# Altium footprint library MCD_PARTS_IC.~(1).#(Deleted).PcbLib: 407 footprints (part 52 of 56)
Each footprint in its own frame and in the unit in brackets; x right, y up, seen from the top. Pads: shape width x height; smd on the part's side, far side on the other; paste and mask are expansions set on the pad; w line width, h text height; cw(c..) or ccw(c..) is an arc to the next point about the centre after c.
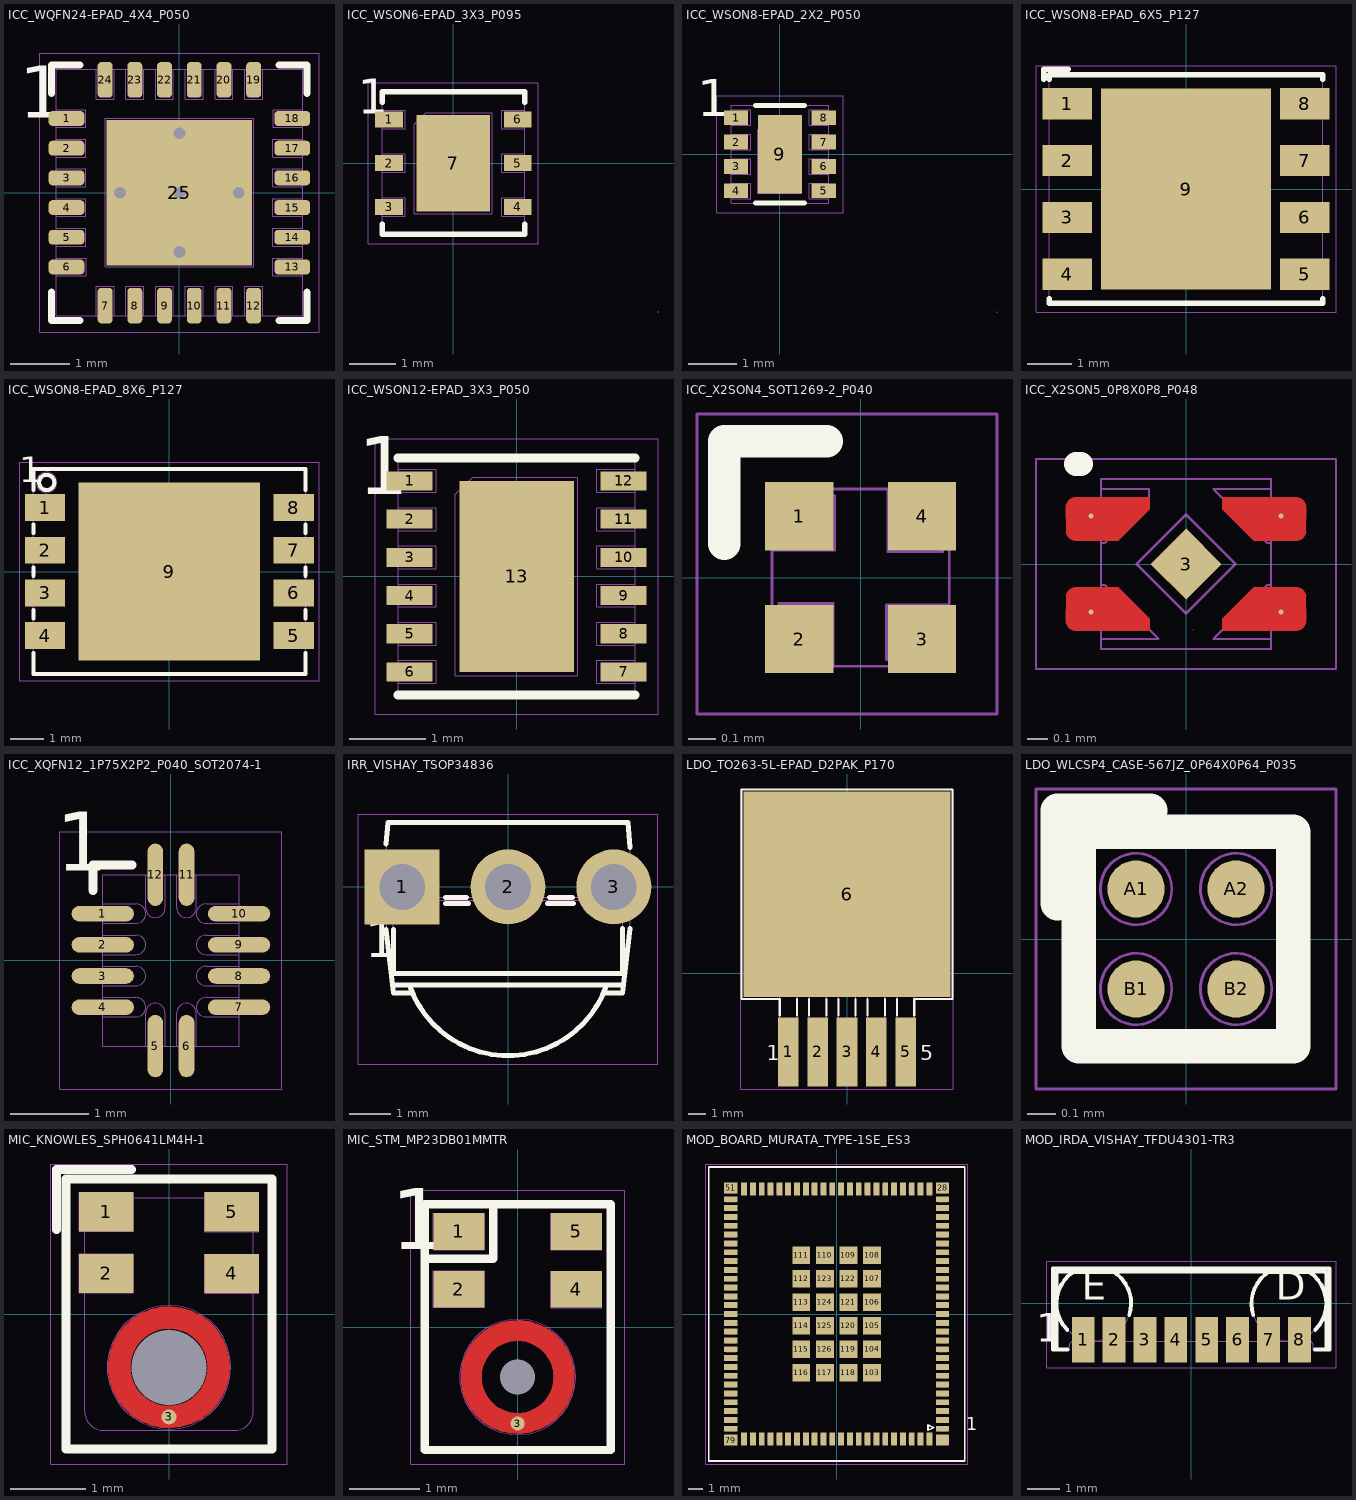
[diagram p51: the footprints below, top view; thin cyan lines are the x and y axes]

## ICC_WQFN24-EPAD_4X4_P050 [mm] "MCD-04320"
height 0.8
pads (25):
  rrect50% 0.6x0.25 smd mask+0.05: 1(-1.9,1.25) 2(-1.9,0.75) 3(-1.9,0.25) 4(-1.9,-0.25) 5(-1.9,-0.75) 6(-1.9,-1.25) 13(1.9,-1.25) 14(1.9,-0.75) 15(1.9,-0.25) 16(1.9,0.25) 17(1.9,0.75) 18(1.9,1.25)
  rrect50% 0.25x0.6 smd mask+0.05: 7(-1.25,-1.9) 8(-0.75,-1.9) 9(-0.25,-1.9) 10(0.25,-1.9) 11(0.75,-1.9) 12(1.25,-1.9) 19(1.25,1.9) 20(0.75,1.9) 21(0.25,1.9) 22(-0.25,1.9) 23(-0.75,1.9) 24(-1.25,1.9)
  rect 2.45x2.45 smd paste-10 mask+0.05: 25(0,0)
via 0,0 diameter 0.45 hole 0.2
via -1,0 diameter 0.45 hole 0.2
via 0,1 diameter 0.45 hole 0.2
via 1,0 diameter 0.45 hole 0.2
via 0,-1 diameter 0.45 hole 0.2
Top Overlay:
  lines w0.12: -2.15,-1.675 -2.15,-2.15 -1.675,-2.15 ; -2.15,1.675 -2.15,2.15 -1.675,2.15 ; 1.675,-2.15 2.15,-2.15 2.15,-1.675 ; 1.675,2.15 2.15,2.15 2.15,1.675
  text "1" at -2.7,0.975 h1.5
Top Paste:
  rectangle: -1.1,0.1 -0.1,1.1
  region: -0.1,-1.1 -0.1,-0.1 -1.1,-0.1 -1.1,-1.1
  region: 1.1,-0.1 0.1,-0.1 0.1,-1.1 1.1,-1.1
  region: 0.1,1.1 0.1,0.1 1.1,0.1 1.1,1.1
M14-Top Assembly:
  lines w0.01: -2.075,-1.4 -1.575,-1.4 -1.575,-1.1 -2.075,-1.1 ; -2.075,-0.9 -1.575,-0.9 -1.575,-0.6 -2.075,-0.6 ; -2.075,-0.4 -1.575,-0.4 -1.575,-0.1 -2.075,-0.1 ; -2.075,0.1 -1.575,0.1 -1.575,0.4 -2.075,0.4 ; -2.075,0.6 -1.575,0.6 -1.575,0.9 -2.075,0.9 ; -2.075,1.1 -1.575,1.1 -1.575,1.4 -2.075,1.4 ; -1.4,-2.075 -1.4,-1.575 -1.1,-1.575 -1.1,-2.075 ; -1.4,2.075 -1.4,1.575 -1.1,1.575 -1.1,2.075 ; -0.9,-2.075 -0.9,-1.575 -0.6,-1.575 -0.6,-2.075 ; -0.9,2.075 -0.9,1.575 -0.6,1.575 -0.6,2.075 ; -0.4,-2.075 -0.4,-1.575 -0.1,-1.575 -0.1,-2.075 ; -0.4,2.075 -0.4,1.575 -0.1,1.575 -0.1,2.075 ; 0.1,-2.075 0.1,-1.575 0.4,-1.575 0.4,-2.075 ; 0.1,2.075 0.1,1.575 0.4,1.575 0.4,2.075 ; 0.6,-2.075 0.6,-1.575 0.9,-1.575 0.9,-2.075 ; 0.6,2.075 0.6,1.575 0.9,1.575 0.9,2.075 ; 1.1,-2.075 1.1,-1.575 1.4,-1.575 1.4,-2.075 ; 1.1,2.075 1.1,1.575 1.4,1.575 1.4,2.075 ; 2.075,-1.4 1.575,-1.4 1.575,-1.1 2.075,-1.1 ; 2.075,-0.9 1.575,-0.9 1.575,-0.6 2.075,-0.6 ; 2.075,-0.4 1.575,-0.4 1.575,-0.1 2.075,-0.1 ; 2.075,0.1 1.575,0.1 1.575,0.4 2.075,0.4 ; 2.075,0.6 1.575,0.6 1.575,0.9 2.075,0.9 ; 2.075,1.1 1.575,1.1 1.575,1.4 2.075,1.4 ; -2.075,-2.075 -2.075,2.075 2.075,2.075 2.075,-2.075 -2.075,-2.075 ; -1.25,-1.25 1.25,-1.25 1.25,1.25 -1.25,1.25 -1.25,-1.25
  text "'.Designator'" at -2,-0.5 h0.75
  text "6" at -2.025,-1.125 h0.65
  text "24" at -1.58,1.625 h0.65
  text "19" at 0.97,1.625 h0.65
  text "18" at 2.025,0.975 h0.65
  text "13" at 2.025,-1.525 h0.65
  text "12" at 0.975,-2.025 h0.65
  text "7" at -1.4,-2.025 h0.65
  text "1" at -2.05,1.325 h0.65
  text "25" at -0.3,-0.225 h0.65
M16-Top Courtyard:
  lines w0.01: -2.35,-2.35 2.35,-2.35 2.35,2.35 -2.35,2.35 -2.35,-2.35
3D body "TXS02612RTWR_3D.stp": height 0.8, standoff 0, extent -2,-2 2,2

## ICC_WSON6-EPAD_3X3_P095 [mm] "MCD-02563"
height 0.8
pads (7):
  rect 0.6x0.35 smd paste+0 mask+0.05: 1(-1.4,0.95) 2(-1.4,0) 3(-1.4,-0.95) 4(1.4,-0.95) 5(1.4,0) 6(1.4,0.95)
  rect 1.6x2.1 smd paste+0 mask+0.05: 7(0,0)
Top Overlay:
  lines w0.12: -1.55,-1.325 -1.55,-1.55 1.55,-1.55 1.55,-1.325 ; -1.55,1.325 -1.55,1.55 1.55,1.55 1.55,1.325
  text "1" at -2.075,0.825 h1.3
M14-Top Assembly:
  lines w0.01: -1.55,-1.15 -1.05,-1.15 -1.05,-0.75 -1.55,-0.75 ; -1.55,-0.2 -1.05,-0.2 -1.05,0.2 -1.55,0.2 ; -1.55,0.75 -1.05,0.75 -1.05,1.15 -1.55,1.15 ; 1.55,-1.15 1.05,-1.15 1.05,-0.75 1.55,-0.75 ; 1.55,-0.2 1.05,-0.2 1.05,0.2 1.55,0.2 ; 1.55,0.75 1.05,0.75 1.05,1.15 1.55,1.15 ; -0.6,1.1 0.85,1.1 0.85,-1.1 -0.85,-1.1 -0.85,0.85 -0.6,1.1 ; -0.6,1.1 -0.6,1.1 ; -1.55,-1.55 1.55,-1.55 1.55,1.55 -1.55,1.55 -1.55,-1.55
  text "6" at 1.2,0.8 h0.5
  text "4" at 1.2,-1.1 h0.5
  text "'.Designator'" at -2,-0.5 h0.75
  text "1" at -1.4,0.8 h0.5
  text "3" at -1.4,-1.1 h0.5
M16-Top Courtyard:
  lines w0.01: 4.45,-3.25 4.45,-3.225 ; -1.85,-1.75 -1.85,1.75 1.85,1.75 1.85,-1.75 -1.85,-1.75
3D body: height 0.8, standoff 0, extent -1.55,-1.55 1.55,1.55
3D body: height 0.81, standoff 0.8, extent -1.325,0.926 -0.927,1.325
3D body "User Library-WSON-6.STEP": height 0.75, standoff 0, extent -1.51,-1.5 1.51,1.5

## ICC_WSON8-EPAD_2X2_P050 [mm] "MCD-02194"
height 0.8
pads (9):
  rect 0.5x0.3 smd paste+0 mask+0.05: 1(-0.9,0.75) 2(-0.9,0.25) 3(-0.9,-0.25) 4(-0.9,-0.75) 5(0.9,-0.75) 6(0.9,-0.25) 7(0.9,0.25) 8(0.9,0.75)
  rect 0.9x1.6 smd paste+0 mask+0.05: 9(0,0)
Top Overlay:
  lines w0.1: -0.5,-1 0.5,-1 ; -0.5,1 0.5,1
  text "1" at -1.7,0.525 h1.3
M14-Top Assembly:
  lines w0.01: -1,-0.91 -0.6,-0.91 -0.6,-0.59 -1,-0.59 ; -1,-0.41 -0.6,-0.41 -0.6,-0.09 -1,-0.09 ; -1,0.09 -0.6,0.09 -0.6,0.41 -1,0.41 ; -1,0.59 -0.6,0.59 -0.6,0.91 -1,0.91 ; -1,-1 1,-1 1,1 -1,1 -1,-1 ; -0.45,-0.8 -0.45,0.5 -0.15,0.8 0.45,0.8 0.45,-0.8 -0.45,-0.8 ; 0.6,-0.91 0.6,-0.59 1,-0.59 1,-0.91 0.6,-0.91 ; 0.6,-0.41 0.6,-0.09 1,-0.09 1,-0.41 0.6,-0.41 ; 0.6,0.09 0.6,0.41 1,0.41 1,0.09 0.6,0.09 ; 0.6,0.59 0.6,0.91 1,0.91 1,0.59 0.6,0.59
  text "'.Designator'" at -2,-0.5 h0.75
  text "1" at -0.9,0.575 h0.5
  text "4" at -0.925,-0.9 h0.5
  text "5" at 0.7,-0.9 h0.5
  text "8" at 0.7,0.575 h0.5
M16-Top Courtyard:
  lines w0.01: 4.45,-3.25 4.45,-3.225 ; -1.3,-1.2 -1.3,1.2 1.3,1.2 1.3,-1.2 -1.3,-1.2
3D body "User Library-SON8-2x2mm-1.STEP": height 0.77, standoff -0.03, extent -1,-1 1,1
3D body: height 0.8, standoff 0, extent -1,-1 1,1
3D body: height 0.81, standoff 0.8, extent -0.873,0.526 -0.475,0.925

## ICC_WSON8-EPAD_6X5_P127 [mm] "MCD-02498"
height 0.8
pads (9):
  rect 1.1x0.7 smd paste+0 mask+0.05: 1(-2.65,1.905) 2(-2.65,0.635) 3(-2.65,-0.635) 4(-2.65,-1.905) 5(2.65,-1.905) 6(2.65,-0.635) 7(2.65,0.635) 8(2.65,1.905)
  rect 3.8x4.5 smd paste+0 mask+0.05: 9(0,0)
Top Overlay:
  lines w0.12: -3.175,2.45 -3.175,2.675 -2.625,2.675 ; -3.05,-2.45 -3.05,-2.55 3.05,-2.55 3.05,-2.45 ; -3.05,2.45 -3.05,2.55 3.05,2.55 3.05,2.45
M14-Top Assembly:
  lines w0.01: -3.05,-2.159 -2.4,-2.159 -2.4,-1.651 -3.05,-1.651 ; -3.05,-0.889 -2.4,-0.889 -2.4,-0.381 -3.05,-0.381 ; -3.05,0.381 -2.4,0.381 -2.4,0.889 -3.05,0.889 ; -3.05,1.651 -2.4,1.651 -2.4,2.159 -3.05,2.159 ; 3.047,-2.156 2.397,-2.156 2.397,-1.648 3.047,-1.648 ; 3.047,-0.886 2.397,-0.886 2.397,-0.378 3.047,-0.378 ; 3.047,0.384 2.397,0.384 2.397,0.892 3.047,0.892 ; 3.047,1.654 2.397,1.654 2.397,2.162 3.047,2.162 ; -3.05,-2.55 -3.05,2.55 3.05,2.55 3.05,-2.55 -3.05,-2.55 ; -1.725,-2.025 -1.725,2.025 1.725,2.025 1.725,-2.025 -1.725,-2.025
  text "8" at 2.636,1.668 h0.75
  text "7" at 2.639,0.398 h0.75
  text "6" at 2.635,-0.872 h0.75
  text "5" at 2.635,-2.138 h0.75
  text "4" at -2.96,-2.145 h0.75
  text "3" at -2.951,-0.872 h0.75
  text "2" at -2.954,0.394 h0.75
  text "1" at -2.882,1.664 h0.75
  text "9" at -0.158,-0.237 h0.75
  text "'.Designator'" at -2,-0.5 h0.75
M16-Top Courtyard:
  lines w0.01: -3.35,-2.75 -3.35,2.75 3.35,2.75 3.35,-2.75 -3.35,-2.75
3D body "8 WSON.STEP": height 0.75, standoff 0, extent -3,-2.5 3,2.5

## ICC_WSON8-EPAD_8X6_P127 [mm]
height 0.8
pads (9):
  rect 1.2x0.8 smd paste+0 mask+0.05: 1(-3.7,1.905) 2(-3.7,0.635) 3(-3.7,-0.635) 4(-3.7,-1.905) 5(3.7,-1.905) 6(3.7,-0.635) 7(3.7,0.635) 8(3.7,1.905)
  rect 5.4x5.3 smd paste+0 mask+0.05: 9(0,0)
Top Overlay:
  circle w0.12: c-3.65,2.65 r0.226
  lines w0.12: -4.05,-2.425 -4.05,-3.05 4.05,-3.05 4.05,-2.425 ; -4.05,-1.4 -4.05,-1.15 ; -4.05,-0.125 -4.05,0.125 ; -4.05,1.15 -4.05,1.4 ; -4.05,2.425 -4.05,3.05 4.05,3.05 4.05,2.425 ; 4.05,-1.4 4.05,-1.15 ; 4.05,-0.125 4.05,0.125 ; 4.05,1.15 4.05,1.4
  text "1" at -4.475,2.4 h1.3
M14-Top Assembly:
  circle w0.01: c-3.65,2.65 r0.304
  lines w0.01: -4.05,-2.159 -3.45,-2.159 -3.45,-1.651 -4.05,-1.651 ; -4.05,-0.889 -3.45,-0.889 -3.45,-0.381 -4.05,-0.381 ; -4.05,0.381 -3.45,0.381 -3.45,0.889 -4.05,0.889 ; -4.05,1.651 -3.45,1.651 -3.45,2.159 -4.05,2.159 ; 4.05,-2.159 3.45,-2.159 3.45,-1.651 4.05,-1.651 ; 4.05,-0.889 3.45,-0.889 3.45,-0.381 4.05,-0.381 ; 4.05,0.381 3.45,0.381 3.45,0.889 4.05,0.889 ; 4.05,1.651 3.45,1.651 3.45,2.159 4.05,2.159 ; -4.05,-3.05 -4.05,3.05 4.05,3.05 4.05,-3.05 -4.05,-3.05 ; -2.4,-2.35 2.4,-2.35 2.4,2.35 -2.4,2.35 -2.4,-2.35
  text "'.Designator'" at -2,0.5 h0.75
  text "9" at -0.15,-0.2 h0.75
  text "1" at -3.85,1.65 h0.75
  text "4" at -3.9,-2.15 h0.75
  text "5" at 3.6,-2.15 h0.75
  text "8" at 3.6,1.65 h0.75
M16-Top Courtyard:
  lines w0.01: -4.45,-3.25 -4.45,2.35 -4.45,3.25 4.45,3.25 4.45,2.8 4.45,-3.225 4.45,-3.25 -4.45,-3.25
3D body "WSON-8_6x8mm.STEP": height 0.81, standoff -0.07, extent -4,-3 4,3
3D body: height 0.8, standoff 0, extent -4.05,-3.05 4.05,3.05
3D body: height 0.81, standoff 0.8, extent -3.648,2.25 -3.25,2.65

## ICC_WSON12-EPAD_3X3_P050 [mm]
height 0.8
pads (13):
  rect 0.6x0.25 smd paste+0 mask+0.05: 1(-1.4,1.25) 2(-1.4,0.75) 3(-1.4,0.25) 4(-1.4,-0.25) 5(-1.4,-0.75) 6(-1.4,-1.25) 7(1.4,-1.25) 8(1.4,-0.75) 9(1.4,-0.25) 10(1.4,0.25) 11(1.4,0.75) 12(1.4,1.25)
  rect 1.5x2.5 smd paste+0 mask+0.05: 13(0,0)
Top Overlay:
  lines w0.12: -1.55,-1.55 1.55,-1.55 ; -1.55,1.55 1.55,1.55
  text "1" at -2.075,0.825 h1.3
M14-Top Assembly:
  lines w0.01: -1.55,-1.4 -1.05,-1.4 -1.05,-1.1 -1.55,-1.1 ; -1.55,-0.9 -1.05,-0.9 -1.05,-0.6 -1.55,-0.6 ; -1.55,-0.4 -1.05,-0.4 -1.05,-0.1 -1.55,-0.1 ; -1.55,0.1 -1.05,0.1 -1.05,0.4 -1.55,0.4 ; -1.55,0.6 -1.05,0.6 -1.05,0.9 -1.55,0.9 ; -1.55,1.1 -1.05,1.1 -1.05,1.4 -1.55,1.4 ; 1.55,-1.4 1.05,-1.4 1.05,-1.1 1.55,-1.1 ; 1.55,-0.9 1.05,-0.9 1.05,-0.6 1.55,-0.6 ; 1.55,-0.4 1.05,-0.4 1.05,-0.1 1.55,-0.1 ; 1.55,0.1 1.05,0.1 1.05,0.4 1.55,0.4 ; 1.55,0.6 1.05,0.6 1.05,0.9 1.55,0.9 ; 1.55,1.1 1.05,1.1 1.05,1.4 1.55,1.4 ; -1.55,-1.55 1.55,-1.55 1.55,1.55 -1.55,1.55 -1.55,-1.55 ; -0.8,-1.3 -0.8,1.075 -0.575,1.3 0.8,1.3 0.8,-1.3 -0.8,-1.3
  text "13" at -0.225,-0.175 h0.5
  text "12" at 1.1,1.1 h0.5
  text "7" at 1.2,-1.4 h0.5
  text "'.Designator'" at -2,-0.5 h0.75
  text "1" at -1.4,1.1 h0.5
  text "6" at -1.4,-1.425 h0.5
M16-Top Courtyard:
  lines w0.01: -1.85,-1.8 -1.85,1.8 1.85,1.8 1.85,-1.8 -1.85,-1.8
3D body: height 0.81, standoff 0.8, extent -1.346,0.896 -0.946,1.296
3D body: height 0.8, standoff 0, extent -1.55,-1.55 1.55,1.55

## ICC_X2SON4_SOT1269-2_P040 [mm] "MCD-03125"
height 0.35
pads (4):
  rect 0.25x0.25 smd mask+0.05: 1(-0.225,0.225) 2(-0.225,-0.225) 3(0.225,-0.225) 4(0.225,0.225)
Top Overlay:
  lines w0.12: -0.5,0.125 -0.5,0.5 -0.475,0.5 -0.125,0.5
M14-Top Assembly:
  lines w0.01: -0.325,0.1 -0.095,0.1 -0.095,0.3 -0.275,0.3 cw(c-0.325,0.3) -0.325,0.25 ; -0.25,-0.325 ccw(c-0.3,-0.325) -0.3,-0.275 -0.3,-0.095 -0.1,-0.095 -0.1,-0.325 ; 0.1,0.325 0.1,0.095 0.3,0.095 0.3,0.275 cw(c0.3,0.325) 0.25,0.325 ; 0.325,-0.25 ccw(c0.325,-0.3) 0.275,-0.3 0.095,-0.3 0.095,-0.1 0.325,-0.1 ; -0.325,-0.325 0.325,-0.325 0.325,0.325 -0.325,0.325 -0.325,-0.325
  text "'.Designator'" at -2,-0.5 h0.75
  text "1" at -0.225,0.125 h0.25
  text "2" at -0.25,-0.275 h0.25
  text "3" at 0.15,-0.275 h0.25
  text "4" at 0.15,0.125 h0.25
M16-Top Courtyard:
  lines w0.01: -0.6,-0.5 0.5,-0.5 0.5,0.6 -0.6,0.6 -0.6,-0.5
3D body: height 0.36, standoff 0.35, extent -0.285,0.08 -0.085,0.28
3D body: height 0.35, standoff 0, extent -0.325,-0.325 0.325,0.325

## ICC_X2SON5_0P8X0P8_P048 [mm] "MCD-03119"
height 0.4
pads (5):
  round 0.025 smd mask+0.05: 1(-0.475,0.24) 2(-0.475,-0.24) 4(0.475,-0.24) 5(0.475,0.24)
  rect 0.25x0.25 smd rot 45 mask+0.05: 3(0,0)
Top Layer:
  region: 0.34,-0.115 0.18,-0.275 0.18,-0.335 0.55,-0.335 0.56,-0.335 0.578,-0.327 0.592,-0.313 0.6,-0.295 0.6,-0.285 0.6,-0.165 0.6,-0.155 0.592,-0.137 0.578,-0.123 0.56,-0.115 0.55,-0.115
  region: -0.34,-0.115 -0.18,-0.275 -0.18,-0.335 -0.55,-0.335 -0.56,-0.335 -0.578,-0.327 -0.592,-0.313 -0.6,-0.295 -0.6,-0.285 -0.6,-0.165 -0.6,-0.155 -0.592,-0.137 -0.578,-0.123 -0.56,-0.115 -0.55,-0.115
  region: 0.34,0.115 0.18,0.275 0.18,0.335 0.55,0.335 0.56,0.335 0.578,0.327 0.592,0.313 0.6,0.295 0.6,0.285 0.6,0.165 0.6,0.155 0.592,0.137 0.578,0.123 0.56,0.115 0.55,0.115
  region: -0.34,0.115 -0.18,0.275 -0.18,0.335 -0.55,0.335 -0.56,0.335 -0.578,0.327 -0.592,0.313 -0.6,0.295 -0.6,0.285 -0.6,0.165 -0.6,0.155 -0.592,0.137 -0.578,0.123 -0.56,0.115 -0.55,0.115
  lines w0.001: 0.035,-0.33 0.035,-0.33
Top Overlay:
  lines w0.12: -0.55,0.5 -0.525,0.5
M14-Top Assembly:
  lines w0.01: -0.425,-0.425 0.425,-0.425 0.425,0.425 -0.425,0.425 -0.425,-0.425 ; -0.425,-0.375 -0.425,-0.105 -0.407,-0.105 -0.137,-0.375 -0.425,-0.375 ; -0.425,0.105 -0.407,0.105 -0.186,0.326 -0.186,0.375 -0.425,0.375 -0.425,0.105 ; -0.247,0 0,-0.247 0.247,0 0,0.247 -0.247,0 ; 0.137,-0.375 0.407,-0.105 0.425,-0.105 0.425,-0.375 0.137,-0.375 ; 0.137,0.375 0.407,0.105 0.425,0.105 0.425,0.375 0.137,0.375
  text "4" at 0.25,-0.3 h0.25
  text "'.Designator'" at -2,-0.5 h0.75
  text "1" at -0.35,0.175 h0.25
  text "2" at -0.35,-0.325 h0.25
  text "3" at -0.05,-0.075 h0.25
  text "5" at 0.25,0.175 h0.25
M16-Top Courtyard:
  lines w0.01: -0.75,-0.525 -0.75,0.525 0.75,0.525 0.75,-0.525 -0.75,-0.525
3D body: height 0.41, standoff 0.4, extent -0.375,0.175 -0.175,0.375
3D body: height 0.4, standoff 0, extent -0.425,-0.425 0.425,0.425

## ICC_XQFN12_1P75X2P2_P040_SOT2074-1 [mm] "MCD-03404"
height 1
pads (12):
  rrect100% 0.8x0.2 smd mask+0.05: 1(-0.875,0.6) 2(-0.875,0.2) 3(-0.875,-0.2) 4(-0.875,-0.6) 7(0.875,-0.6) 8(0.875,-0.2) 9(0.875,0.2) 10(0.875,0.6)
  rrect100% 0.2x0.8 smd mask+0.05: 5(-0.2,-1.1) 6(0.2,-1.1) 11(0.2,1.1) 12(-0.2,1.1)
Top Overlay:
  lines w0.12: -1,0.9 -1,1.225 -0.5,1.225
  text "1" at -1.475,0.9 h1.3
M14-Top Assembly:
  lines w0.01: -0.875,-0.725 -0.45,-0.725 ccw(c-0.45,-0.6) -0.325,-0.6 ccw(c-0.45,-0.6) -0.45,-0.475 -0.875,-0.475 ; -0.875,-0.325 -0.45,-0.325 ccw(c-0.45,-0.2) -0.325,-0.2 ccw(c-0.45,-0.2) -0.45,-0.075 -0.875,-0.075 ; -0.875,0.075 -0.45,0.075 ccw(c-0.45,0.2) -0.325,0.2 ccw(c-0.45,0.2) -0.45,0.325 -0.875,0.325 ; -0.875,0.475 -0.45,0.475 ccw(c-0.45,0.6) -0.325,0.6 ccw(c-0.45,0.6) -0.45,0.725 -0.875,0.725 ; -0.325,-1.1 -0.325,-0.675 cw(c-0.2,-0.675) -0.2,-0.55 cw(c-0.2,-0.675) -0.075,-0.675 -0.075,-1.1 ; -0.325,1.1 -0.325,0.675 ccw(c-0.2,0.675) -0.2,0.55 ccw(c-0.2,0.675) -0.075,0.675 -0.075,1.1 ; 0.075,-1.1 0.075,-0.675 cw(c0.2,-0.675) 0.2,-0.55 cw(c0.2,-0.675) 0.325,-0.675 0.325,-1.1 ; 0.075,1.1 0.075,0.675 ccw(c0.2,0.675) 0.2,0.55 ccw(c0.2,0.675) 0.325,0.675 0.325,1.1 ; 0.875,-0.725 0.45,-0.725 cw(c0.45,-0.6) 0.325,-0.6 cw(c0.45,-0.6) 0.45,-0.475 0.875,-0.475 ; 0.875,-0.325 0.45,-0.325 cw(c0.45,-0.2) 0.325,-0.2 cw(c0.45,-0.2) 0.45,-0.075 0.875,-0.075 ; 0.875,0.075 0.45,0.075 cw(c0.45,0.2) 0.325,0.2 cw(c0.45,0.2) 0.45,0.325 0.875,0.325 ; 0.875,0.475 0.45,0.475 cw(c0.45,0.6) 0.325,0.6 cw(c0.45,0.6) 0.45,0.725 0.875,0.725 ; -0.875,-1.1 -0.875,1.1 0.875,1.1 0.875,-1.1 -0.875,-1.1 ; -0.75,-0.725 -0.75,-0.725 ; -0.75,-0.325 -0.75,-0.325 ; -0.75,0.075 -0.75,0.075 ; -0.75,0.475 -0.75,0.475 ; -0.325,-0.975 -0.325,-0.975 ; -0.075,0.975 -0.075,0.975 ; 0.075,-0.975 0.075,-0.975 ; 0.325,0.975 0.325,0.975 ; 0.75,-0.725 0.75,-0.725 ; 0.75,-0.325 0.75,-0.325 ; 0.75,0.075 0.75,0.075 ; 0.75,0.475 0.75,0.475
  text "1" at -0.8,0.4 h0.7
  text "'.Designator'" at -2,-0.5 h0.75
M16-Top Courtyard:
  lines w0.01: -1.425,-1.65 -1.425,1.65 1.425,1.65 1.425,-1.65 -1.425,-1.65
3D body: height 0.51, standoff 0.5, extent -0.699,0.625 -0.4,0.925
3D body: height 0.5, standoff 0, extent -0.875,-1.1 0.875,1.1

## IRR_VISHAY_TSOP34836 [mm] "MCD-01692"
height 8.25
pads (3):
  rect 1.8x1.8 hole 1.1 mask+0.05: 1(-2.54,0)
  round 1.8 hole 1.1 mask+0.05: 2(0,0) 3(2.54,0)
Top Overlay:
  lines w0.12: -2.925,-1.025 -2.75,-2.55 -2.29,-2.55 ; -2.925,1.025 -2.875,1.55 2.875,1.55 2.925,0.95 ; -2.774,-2.35 2.774,-2.35 ; -2.75,-1.025 -2.75,-2.075 2.75,-2.075 2.75,-1 ; -2.369,-2.348 ccw(c0,-1.55) 2.369,-2.348 ; -1.5,-0.4 -0.95,-0.4 ; -1.5,-0.25 -1,-0.25 ; 0.95,-0.4 1.575,-0.4 ; 1,-0.25 1.55,-0.25 ; 2.29,-2.55 2.75,-2.55 2.925,-1
  text "1" at -3.425,-1.975 h1.5
M14-Top Assembly:
  lines w0.01: -2.774,-2.35 2.774,-2.35 ; -2.369,-2.348 ccw(c0,-1.55) 2.369,-2.348 ; -2.29,-2.55 -2.75,-2.55 -3,-0.25 ; 2.29,-2.55 2.75,-2.55 3,-0.25 ; -3,-0.25 3,-0.25 ; -3,-0.25 -2.875,1.55 2.875,1.55 3,-0.25 ; -2.89,-0.25 -2.19,-0.25 -2.19,0.25 -2.89,0.25 -2.89,-0.25 ; -2.75,-2.075 -2.75,-0.325 2.75,-0.325 2.75,-2.075 -2.75,-2.075 ; -0.35,-0.25 0.35,-0.25 0.35,0.25 -0.35,0.25 -0.35,-0.25 ; 2.19,-0.25 2.89,-0.25 2.89,0.25 2.19,0.25 2.19,-0.25
  text "3" at 2.4,-0.25 h0.75
  text "2" at -0.175,-0.25 h0.75
  text "'.Designator'" at -2,-1.7 h0.75
  text "1" at -2.65,-0.25 h0.75
M16-Top Courtyard:
  lines w0.01: -3.6,-4.25 -3.6,1.75 3.6,1.75 3.6,-4.25 -3.6,-4.25
3D body: height 8.25, standoff 0, extent -3,-4.05 3,1.55
3D body "TSOP34836.stp": height 8.25, standoff -22.25, extent -3,-4 3,1.55

## LDO_TO263-5L-EPAD_D2PAK_P170 [mm]
height 4.6
pads (6):
  rect 1.2x4 smd mask+0.05: 1(-3.4,-4.575) 2(-1.7,-4.575) 3(0,-4.575) 4(1.7,-4.575) 5(3.4,-4.575)
  rect 12x11.9 smd mask+0.05: 6(0,4.575)
Top Overlay:
  lines w0.12: -3.9,-2.45 -3.9,-1.5 -6.125,-1.5 -6.125,-0.85 -6.125,10.65 6.125,10.65 6.125,-1.5 3.9,-1.5 3.9,-2.45 ; -2.9,-2.45 -2.9,-1.5 ; -2.2,-2.45 -2.2,-1.5 ; -1.2,-2.45 -1.2,-1.5 ; -0.5,-2.45 -0.5,-1.5 ; 0.5,-2.45 0.5,-1.5 ; 1.2,-2.45 1.2,-1.5 ; 2.2,-2.45 2.2,-1.5 ; 2.9,-2.45 2.9,-1.5
  text "5" at 4.25,-5.35 h1.5
  text "1" at -4.65,-5.35 h1.5
M14-Top Assembly:
  lines w0.01: -5.5,8.325 -5.5,9.325 -4.8,10.025 ; -5.5,8.325 -5.5,-0.875 5.5,-0.875 5.5,8.325 ; -5.5,8.325 0,8.325 5.5,8.325 ; -4.8,10.025 4.8,10.025 5.5,9.325 ; -4.8,10.025 -4.8,10.025 ; -3.9,-3.175 -2.9,-3.175 ; -3.9,-3.175 -3.9,-5.975 -2.9,-5.975 -2.9,-3.175 ; -3.9,-3.175 -3.9,-0.875 -2.9,-0.875 -2.9,-3.175 ; -3.9,-3.175 -2.9,-3.175 ; -2.2,-3.175 -1.2,-3.175 ; -2.2,-3.175 -2.2,-5.975 -1.2,-5.975 -1.2,-3.175 ; -2.2,-3.175 -2.2,-0.875 -1.2,-0.875 -1.2,-3.175 ; -2.2,-3.175 -1.2,-3.175 ; -0.5,-3.175 0.5,-3.175 ; -0.5,-3.175 -0.5,-0.875 0.5,-0.875 0.5,-3.175 ; -0.5,-3.175 -0.5,-5.975 0.5,-5.975 0.5,-3.175 ; -0.5,-3.175 0.5,-3.175 ; 1.2,-3.175 2.2,-3.175 ; 1.2,-3.175 1.2,-5.975 2.2,-5.975 2.2,-3.175 ; 1.2,-3.175 1.2,-0.875 2.2,-0.875 2.2,-3.175 ; 1.2,-3.175 2.2,-3.175 ; 2.9,-3.175 3.9,-3.175 ; 2.9,-3.175 2.9,-5.975 3.9,-5.975 3.9,-3.175 ; 2.9,-3.175 2.9,-0.875 3.9,-0.875 3.9,-3.175 ; 2.9,-3.175 3.9,-3.175 ; 5.5,8.325 5.5,9.325 ; 5.5,9.325 5.5,9.325
  text "'.Designator'" at -2,-0.5 h0.75
  text "2" at -2.125,-5.175 h1.5
  text "3" at -0.425,-5.175 h1.5
  text "1" at -3.525,-5.15 h1.5
  text "4" at 1.3,-5.2 h1.5
  text "5" at 3,-5.2 h1.5
M16-Top Courtyard:
  lines w0.01: -6.15,-6.725 -6.15,10.675 6.15,10.675 6.15,-6.725 -3.75,-6.725 -4.05,-6.725 -6.15,-6.725
3D body: height 4.6, standoff 0, extent -5.5,-0.875 5.5,10.025
3D body "TO-263-5.STEP": height 4.56, standoff 0, extent -5.13,-5.152 5.03,8.863

## LDO_WLCSP4_CASE-567JZ_0P64X0P64_P035 [mm]
height 0.33
pads (4):
  round 0.2 smd mask+0.038: A1(-0.175,0.175) A2(0.175,0.175) B1(-0.175,-0.175) B2(0.175,-0.175)
Top Overlay:
  lines w0.12: -0.45,0.125 -0.45,0.45 -0.125,0.45 ; -0.375,-0.375 -0.375,0.375 0.375,0.375 0.375,-0.375 -0.375,-0.375
M14-Top Assembly:
  circle w0.01: c-0.175,0.175 r0.125
  circle w0.01: c0.175,0.175 r0.125
  circle w0.01: c0.175,-0.175 r0.125
  circle w0.01: c-0.175,-0.175 r0.125
  lines w0.01: -0.32,-0.32 0.32,-0.32 0.32,0.32 -0.32,0.32 -0.32,-0.32
  text "A1" at -0.3,0.1 h0.3
  text "'.Designator'" at -2,-0.5 h0.75
M16-Top Courtyard:
  lines w0.01: -0.525,-0.525 -0.525,-0.05 -0.525,0.525 0.525,0.525 0.525,-0.525 -0.525,-0.525
3D body: height 0.33, standoff 0, extent -0.312,-0.312 0.313,0.313
3D body "WLCSP4.STEP": height 0.45, standoff -0.02, extent -0.337,-0.337 0.338,0.338

## MIC_KNOWLES_SPH0641LM4H-1 [mm] "MCD-01395"
height 1.08
pads (6):
  rect 0.725x0.522 smd mask+0.05: 1(-0.838,1.364) 2(-0.838,0.542) 4(0.838,0.542) 5(0.838,1.364)
  round 0.2 smd mask+0.05: 3(0,-1.373)
  round 0 hole 1 unplated mask+0.05: 6(0,-0.71)
Top Layer:
  circle w0.3: c0,-0.71 r0.663
Top Overlay:
  lines w0.12: -1.5,1.125 -1.5,1.925 -0.5,1.925 ; -1.375,-1.8 1.375,-1.8 1.375,1.8 -1.375,1.8 -1.375,-1.8
Bottom Overlay:
  circle w0.1: c0,-0.71 r0.654
M14-Top Assembly:
  circle w0.01: c0,-0.71 r0.825
  circle w0.01: c0,-0.71 r0.525
  circle w0.01: c0,-0.71 r0.175
  lines w0.01: -1.375,-1.8 -1.375,1.8 1.375,1.8 1.375,-1.8 -1.375,-1.8 ; -1.2,0.285 -0.475,0.285 -0.475,0.805 -1.2,0.805 -1.2,0.285 ; -1.2,1.105 -1.2,1.625 -0.475,1.625 -0.475,1.105 -1.2,1.105 ; -1.125,-1.3 ccw(c-0.875,-1.3) -0.875,-1.55 0.875,-1.55 ccw(c0.875,-1.3) 1.125,-1.3 1.125,1.3 ccw(c0.875,1.3) 0.875,1.55 -0.875,1.55 ccw(c-0.875,1.3) -1.125,1.3 -1.125,-1.3 ; 0.475,0.28 0.475,0.8 1.2,0.8 1.2,0.28 0.475,0.28 ; 0.475,1.1 1.2,1.1 1.2,1.62 0.475,1.62 0.475,1.1
  text "1" at -0.975,1.15 h0.7
  text "2" at -1,0.325 h0.7
  text "4" at 0.65,0.325 h0.7
  text "5" at 0.675,1.15 h0.7
  text "3" at -0.175,-1.6 h0.7
  text "'.Designator'" at 0,0 h0.75
M16-Top Courtyard:
  lines w0.01: -1.575,-2 1.575,-2 1.575,2 -1.575,2 -1.575,-2
3D body: height 0.3, standoff 0, extent -1.375,-1.8 1.375,1.8
3D body: height 1.08, standoff 0.31, extent -1.125,-1.55 1.125,1.55
3D body: height 1.09, standoff 1.08, extent -0.149,-0.85 0.15,-0.55

## MIC_STM_MP23DB01MMTR [mm]
height 1.08
pads (6):
  rect 0.725x0.522 smd mask+0.05: 1(-0.838,1.364) 2(-0.838,0.542) 4(0.838,0.542) 5(0.838,1.364)
  round 0.2 smd mask+0.05: 3(0,-1.373)
  round 0 hole 0.5 unplated mask+0.05: 6(0,-0.71)
Top Layer:
  circle w0.3: c0,-0.71 r0.663
Top Overlay:
  lines w0.12: -1.325,0.975 -0.35,0.975 -0.35,1.74 -0.36,1.75 ; -1.325,-1.75 1.325,-1.75 1.325,1.75 -1.325,1.75 -1.325,-1.75
  text "1" at -1.8,0.825 h1.5
M14-Top Assembly:
  circle w0.01: c0,-0.71 r0.825
  circle w0.01: c0,-0.71 r0.525
  circle w0.01: c0,-0.71 r0.175
  lines w0.01: -1.325,-1.75 -1.325,1.75 1.325,1.75 1.325,-1.75 -1.325,-1.75 ; -1.2,0.285 -0.475,0.285 -0.475,0.805 -1.2,0.805 -1.2,0.285 ; -1.2,1.105 -1.2,1.625 -0.475,1.625 -0.475,1.105 -1.2,1.105 ; 0.475,0.28 0.475,0.8 1.2,0.8 1.2,0.28 0.475,0.28 ; 0.475,1.1 1.2,1.1 1.2,1.62 0.475,1.62 0.475,1.1
  text "1" at -0.975,1.15 h0.7
  text "2" at -1,0.325 h0.7
  text "4" at 0.65,0.325 h0.7
  text "5" at 0.675,1.15 h0.7
  text "3" at -0.175,-1.6 h0.7
  text "'.Designator'" at 0,0 h0.75
M16-Top Courtyard:
  lines w0.01: -1.525,-1.95 1.525,-1.95 1.525,1.95 -1.525,1.95 -1.525,-1.95
3D body: height 1.09, standoff 1.08, extent -0.974,1.225 -0.675,1.525
3D body: height 1.08, standoff 0, extent -1.33,-1.755 1.33,1.755

## MOD_BOARD_MURATA_TYPE-1SE_ES3 [mm] "MCD-01700-ES3"
height 1.2
pads (126):
  rect 0.9x0.4 smd mask+0.05: 1(7.2,-7.8) 2(7.2,-7.2) 3(7.2,-6.6) 4(7.2,-6) 5(7.2,-5.4) 6(7.2,-4.8) 7(7.2,-4.2) 8(7.2,-3.6) 9(7.2,-3) 10(7.2,-2.4) 11(7.2,-1.8) 12(7.2,-1.2) 13(7.2,-0.6) 14(7.2,0) 15(7.2,0.6) 16(7.2,1.2) 17(7.2,1.8) 18(7.2,2.4) 19(7.2,3) 20(7.2,3.6) 21(7.2,4.2) 22(7.2,4.8) 23(7.2,5.4) 24(7.2,6) 25(7.2,6.6) 26(7.2,7.2) 27(7.2,7.8) 52(-7.2,7.8) 53(-7.2,7.2) 54(-7.2,6.6) 55(-7.2,6) 56(-7.2,5.4) 57(-7.2,4.8) 58(-7.2,4.2) 59(-7.2,3.6) 60(-7.2,3) 61(-7.2,2.4) 62(-7.2,1.8) 63(-7.2,1.2) 64(-7.2,0.6) 65(-7.2,0) 66(-7.2,-0.6) 67(-7.2,-1.2) 68(-7.2,-1.8) 69(-7.2,-2.4) 70(-7.2,-3) 71(-7.2,-3.6) 72(-7.2,-4.2) 73(-7.2,-4.8) 74(-7.2,-5.4) 75(-7.2,-6) 76(-7.2,-6.6) 77(-7.2,-7.2) 78(-7.2,-7.8)
  rect 0.9x0.75 smd mask+0.05: 28(7.2,8.575) 51(-7.2,8.575) 79(-7.2,-8.575) 102(7.2,-8.575)
  rect 0.4x0.9 smd mask+0.05: 29(6.3,8.5) 30(5.7,8.5) 31(5.1,8.5) 32(4.5,8.5) 33(3.9,8.5) 34(3.3,8.5) 35(2.7,8.5) 36(2.1,8.5) 37(1.5,8.5) 38(0.9,8.5) 39(0.3,8.5) 40(-0.3,8.5) 41(-0.9,8.5) 42(-1.5,8.5) 43(-2.1,8.5) 44(-2.7,8.5) 45(-3.3,8.5) 46(-3.9,8.5) 47(-4.5,8.5) 48(-5.1,8.5) 49(-5.7,8.5) 50(-6.3,8.5) 80(-6.3,-8.5) 81(-5.7,-8.5) 82(-5.1,-8.5) 83(-4.5,-8.5) 84(-3.9,-8.5) 85(-3.3,-8.5) 86(-2.7,-8.5) 87(-2.1,-8.5) 88(-1.5,-8.5) 89(-0.9,-8.5) 90(-0.3,-8.5) 91(0.3,-8.5) 92(0.9,-8.5) 93(1.5,-8.5) 94(2.1,-8.5) 95(2.7,-8.5) 96(3.3,-8.5) 97(3.9,-8.5) 98(4.5,-8.5) 99(5.1,-8.5) 100(5.7,-8.5) 101(6.3,-8.5)
  rect 1.2x1.2 smd mask+0.05: 103(2.4,-4) 104(2.4,-2.4) 105(2.4,-0.8) 106(2.4,0.8) 107(2.4,2.4) 108(2.4,4) 109(0.8,4) 110(-0.8,4) 111(-2.4,4) 112(-2.4,2.4) 113(-2.4,0.8) 114(-2.4,-0.8) 115(-2.4,-2.4) 116(-2.4,-4) 117(-0.8,-4) 118(0.8,-4) 119(0.8,-2.4) 120(0.8,-0.8) 121(0.8,0.8) 122(0.8,2.4) 123(-0.8,2.4) 124(-0.8,0.8) 125(-0.8,-0.8) 126(-0.8,-2.4)
Top Overlay:
  lines w0.12: -8.7,-10 -8.7,10 8.7,10 8.7,-10 -8.7,-10 ; 6.2,-7.9 6.575,-7.725 6.2,-7.55 6.2,-7.9
  text "1" at 8.8,-8.225 h1.5
M14-Top Assembly:
  drawing of 509 lines, arcs and shapes, not listed
  text "111" at -2.85,3.775 h0.7
  text "110" at -1.25,3.775 h0.7
  text "109" at 0.35,3.775 h0.7
  text "108" at 1.95,3.775 h0.7
  text "112" at -2.85,2.175 h0.7
  text "123" at -1.25,2.175 h0.7
  text "122" at 0.35,2.175 h0.7
  text "107" at 1.95,2.175 h0.7
  text "113" at -2.85,0.575 h0.7
  text "124" at -1.25,0.575 h0.7
  text "121" at 0.35,0.575 h0.7
  text "106" at 1.95,0.575 h0.7
  text "114" at -2.85,-1.025 h0.7
  text "125" at -1.25,-1.025 h0.7
  text "120" at 0.35,-1.025 h0.7
  text "105" at 1.95,-1.025 h0.7
  text "115" at -2.85,-2.625 h0.7
  text "126" at -1.25,-2.625 h0.7
  text "119" at 0.35,-2.625 h0.7
  text "104" at 1.95,-2.625 h0.7
  text "103" at 1.95,-4.2 h0.7
  text "118" at 0.35,-4.2 h0.7
  text "117" at -1.25,-4.2 h0.7
  text "116" at -2.85,-4.2 h0.7
  text "'.Designator'" at -2,-0.5 h0.75
  text "78" at -7.5,-8.025 h0.7
  text "52" at -7.525,7.575 h0.7
  text "51" at -7.475,8.3 h0.7
  text "50" at -6.625,8.275 h0.7
  text "29" at 5.975,8.275 h0.7
  text "1" at 7.1,-8 h0.7
  text "28" at 6.875,8.3 h0.7
  text "27" at 6.875,7.575 h0.7
  text "102" at 6.725,-8.75 h0.7
  text "101" at 5.75,-8.725 h0.7
  text "79" at -7.525,-8.75 h0.7
  text "80" at -6.6,-8.725 h0.7
M16-Top Courtyard:
  lines w0.01: -8.9,-10.2 8.9,-10.2 8.9,10.2 -8.9,10.2 -8.9,-10.2
3D body: height 1.2, standoff 0, extent -8.7,-10 8.7,10
3D body: height 1.21, standoff 1.2, extent 6.903,-8.099 7.5,-7.5

## MOD_IRDA_VISHAY_TFDU4301-TR3 [mm] "MCD-02036"
height 3.1
pads (8):
  rect 0.7x1.4 smd mask+0.05: 1(-3.325,-1.12) 2(-2.375,-1.12) 3(-1.425,-1.12) 4(-0.475,-1.12) 5(0.475,-1.12) 6(1.425,-1.12) 7(2.375,-1.12) 8(3.325,-1.12)
Top Overlay:
  lines w0.12: -4.15,-1.42 -4.15,0.905 cw(c-4.075,0.905) -4.075,0.98 4.075,0.98 cw(c4.075,0.905) 4.15,0.905 4.15,-1.42 ; -3.813,-0.813 cw(c-3,0) -3.621,0.968 -2.379,0.968 cw(c-3,0) -1.906,-0.356 ; -3.8,-1.42 -4.25,-1.42 -4.25,1.08 4.25,1.08 4.25,-1.42 3.8,-1.42 ; 1.906,-0.356 cw(c3,0) 2.379,0.968 3.621,0.968 cw(c3,0) 3.813,-0.813
  text "E" at -3.375,-0.175 h1.5
  text "D" at 2.6,-0.175 h1.5
  text "1" at -4.775,-1.475 h1.5
M14-Top Assembly:
  lines w0.01: -4.15,-1.42 -4.15,0.905 cw(c-4.075,0.905) -4.075,0.98 4.075,0.98 cw(c4.075,0.905) 4.15,0.905 4.15,-1.42 ; -3.55,-1.17 -3.55,-1.42 -3.1,-1.42 -3.1,-1.17 ; -2.6,-1.17 -2.6,-1.42 -2.15,-1.42 -2.15,-1.17 ; -1.65,-1.17 -1.65,-1.42 -1.2,-1.42 -1.2,-1.17 ; -0.7,-1.17 -0.7,-1.42 -0.25,-1.42 -0.25,-1.17 ; 0.25,-1.17 0.25,-1.42 0.7,-1.42 0.7,-1.17 ; 1.2,-1.17 1.2,-1.42 1.65,-1.42 1.65,-1.17 ; 2.15,-1.17 2.15,-1.42 2.6,-1.42 2.6,-1.17 ; 3.1,-1.17 3.1,-1.42 3.55,-1.42 3.55,-1.17 ; -3.625,-1.17 ccw(c-3.625,-1.295) -3.75,-1.295 -3.75,-1.42 -3.875,-1.42 -4.25,-1.42 -4.25,1.08 4.25,1.08 4.25,-1.42 3.75,-1.42 3.75,-1.295 ccw(c3.625,-1.295) 3.625,-1.17 ; -3.625,-1.17 -3.625,-1.17 ; -3.625,-1.17 3.55,-1.17 ; 3.55,-1.17 3.625,-1.17 ; 3.625,-1.17 3.625,-1.17 ; -3.621,0.968 ccw(c-3,0) -2.379,0.968 -3.621,0.968 ; 2.379,0.968 ccw(c3,0) 3.621,0.968 2.379,0.968
  text "'.Designator'" at -2,-0.5 h0.75
  text "1" at -3.425,-1.7 h0.75
  text "8" at 3.175,-1.7 h0.75
  text "EMITTER" at -3.95,-0.15 h0.4
  text "DETECTOR" at 1.8,-0.15 h0.4
M16-Top Courtyard:
  lines w0.01: -4.45,-1.975 4.45,-1.975 4.45,1.3 -4.45,1.3 -4.45,-1.975
3D body: height 1, standoff 0.8, extent -4.25,-1.42 4.25,1.08
3D body: height 0.3, standoff 0, extent -4.15,-0.325 4.15,1.08
3D body: height 1, standoff 0.3, extent -4.15,-1.42 4.15,1.08
3D body: height 1, standoff 0, extent -3.55,-1.425 -3.1,-1.17
3D body: height 0.3, standoff 0, extent -3.55,-1.425 -3.1,-0.475
3D body: height 0.3, standoff 0, extent -2.6,-1.42 -2.15,-0.47
3D body: height 1, standoff 0, extent -2.6,-1.42 -2.15,-1.165
3D body: height 0.3, standoff 0, extent -1.65,-1.42 -1.2,-0.47
3D body: height 1, standoff 0, extent -1.65,-1.42 -1.2,-1.165
3D body: height 0.3, standoff 0, extent -0.7,-1.42 -0.25,-0.47
3D body: height 1, standoff 0, extent -0.7,-1.42 -0.25,-1.165
3D body: height 0.3, standoff 0, extent 0.25,-1.42 0.7,-0.47
3D body: height 1, standoff 0, extent 0.25,-1.42 0.7,-1.165
3D body: height 0.3, standoff 0, extent 1.2,-1.42 1.65,-0.47
3D body: height 1, standoff 0, extent 1.2,-1.42 1.65,-1.165
3D body: height 0.3, standoff 0, extent 2.15,-1.42 2.6,-0.47
3D body: height 1, standoff 0, extent 2.15,-1.42 2.6,-1.165
3D body: height 0.3, standoff 0, extent 3.1,-1.42 3.55,-0.47
3D body: height 1, standoff 0, extent 3.1,-1.42 3.55,-1.165
3D body: height 1.9, standoff 1, extent -4.15,-1.25 4.15,1.075
3D body: height 2.85, standoff 0.69, extent -4.079,-1.077 -1.92,1.077
3D body: height 3.1, standoff 0.94, extent 1.921,-1.077 4.08,1.077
